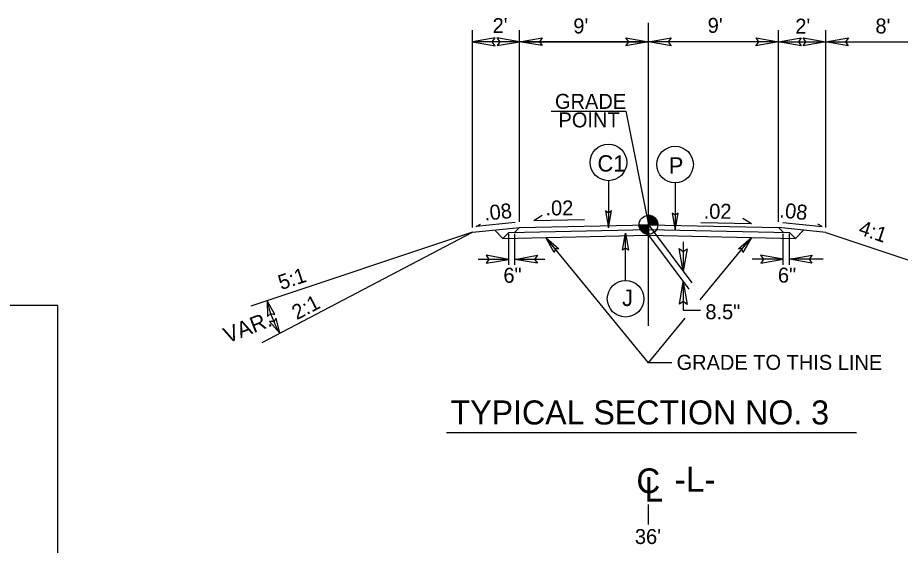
# Model space of a CAD drawing. Extents: x 1718167 to 1721223, y 797898 to 799800.
# Drawn here: x 1719514 to 1719936.5, y 798300.3 to 798552.9 of the extents above; entities that cross this region are included whole.
import ezdxf

# ---------------------------------------------------------------- set-up
doc = ezdxf.new("R2010")
doc.units = 0
for name, color, linetype in [('Old_Level_1', 7, 'Continuous'), ('Old_Level_2', 7, 'Continuous'), ('Prop Dimension Text', 7, 'Continuous'), ('Prop Terminator CELL', 7, 'Continuous'), ('Typical ID Circle CELL', 7, 'Continuous'), ('Typical Slope Point Local CELL', 7, 'Continuous'), ('Typical Terminator CELL', 7, 'Continuous'), ('Typical Text Centerline CELL', 7, 'Continuous'), ('Typical Text Grade Point CELL', 7, 'Continuous'), ('Typical Text ID Circle CELL', 7, 'Continuous'), ('Typical Text Label CELL', 7, 'Continuous')]:
    doc.layers.add(name, color=color, linetype=linetype)

# ---------------------------------------------------------------- blocks, each defined once
blk = doc.blocks.new('TERMINATOR')
at = {"layer": 'Typical Terminator CELL'}
blk.add_lwpolyline([(-0.469, 0.081), (0, 0), (-0.471, -0.083), (-0.411, 0)], close=True, dxfattribs=at)

msp = doc.modelspace()

# ---------------------------------------------------------------- linework, layer by layer
at = {"layer": 'Old_Level_1'}
for p, q in [((1719731.69, 798452.53), (1719731.67, 798546.87)), ((1719754.2, 798455.14), (1719754.22, 798546.88)), ((1719878.2, 798455.11), (1719878.22, 798546.86)), ((1719900.75, 798452.51), (1719900.77, 798546.84)), ((1719754.22, 798541.37), (1719731.67, 798541.36)), ((1719815.92, 798541.35), (1719754.22, 798541.37)), ((1719755.92, 798541.37), (1719815.92, 798541.35)), ((1719878.22, 798541.34), (1719815.92, 798541.35)), ((1719878.22, 798541.34), (1719900.76, 798541.34)), ((1719900.76, 798541.34), (1719955.79, 798541.33)), ((1719769.42, 798508.11), (1719805.11, 798508.1)), ((1719805.11, 798508.1), (1719815.9, 798453.71)), ((1719815.9, 798453.71), (1719815.91, 798458.21)), ((1719731.69, 798450.15), (1719754.24, 798452.44)), ((1719752.17, 798454.86), (1719733.45, 798452.96)), ((1719733.45, 798452.96), (1719735.53, 798454)), ((1719811.4, 798453.71), (1719815.9, 798453.71)), ((1719815.89, 798449.21), (1719815.9, 798453.71)), ((1719815.9, 798453.71), (1719815.89, 798449.21)), ((1719820.4, 798453.71), (1719815.9, 798453.71)), ((1719815.9, 798453.71), (1719836.72, 798425.99)), ((1719900.75, 798450.13), (1719878.2, 798452.42)), ((1719880.27, 798454.83), (1719898.99, 798452.93)), ((1719898.99, 798452.93), (1719896.91, 798453.97)), ((1719731.69, 798450.15), (1719625.59, 798414.76)), ((1719749.03, 798434.58), (1719749.03, 798449.37)), ((1719751.96, 798434.58), (1719751.96, 798449.37)), ((1719815.9, 798448.71), (1719835.3, 798422.88)), ((1719880.42, 798434.65), (1719880.43, 798449.43)), ((1719883.35, 798434.64), (1719883.35, 798449.43)), ((1719900.75, 798450.13), (1719955.77, 798431.77)), ((1719815.99, 798387.74), (1719766.8, 798447.69)), ((1719832.58, 798445.57), (1719832.58, 798431.51)), ((1719840.7, 798417.85), (1719865.18, 798447.69)), ((1719749.03, 798437.21), (1719734.34, 798437.21)), ((1719766.3, 798437.21), (1719751.96, 798437.21)), ((1719880.42, 798437.27), (1719865.53, 798437.27)), ((1719899.48, 798437.28), (1719883.35, 798437.27)), ((1719832.58, 798426.51), (1719832.58, 798412.85)), ((1719832.58, 798412.85), (1719840.85, 798412.85)), ((1719815.99, 798387.74), (1719833.5, 798409.08)), ((1719827.04, 798387.74), (1719815.99, 798387.74))]:
    msp.add_line(p, q, dxfattribs=at)
for points in [[(1719815.95, 798458.21), (1719815.95, 798458.21), (1719815.94, 798453.71)], [(1719816.04, 798458.21), (1719816.03, 798453.71)], [(1719816.13, 798458.2), (1719816.12, 798453.71)], [(1719816.22, 798458.2), (1719816.21, 798453.71)], [(1719816.31, 798458.19), (1719816.3, 798453.71)], [(1719816.4, 798458.18), (1719816.39, 798453.71)], [(1719816.49, 798458.17), (1719816.48, 798453.71)], [(1719816.58, 798458.16), (1719816.57, 798453.71)], [(1719816.67, 798458.15), (1719816.66, 798453.71)], [(1719816.76, 798458.13), (1719816.75, 798453.71)], [(1719816.85, 798458.11), (1719816.84, 798453.71)], [(1719816.94, 798458.09), (1719816.93, 798453.71)], [(1719817.03, 798458.07), (1719817.02, 798453.71)], [(1719817.12, 798458.04), (1719817.11, 798453.71)], [(1719817.21, 798458.02), (1719817.2, 798453.71)], [(1719817.3, 798457.99), (1719817.29, 798453.71)], [(1719817.39, 798457.96), (1719817.38, 798453.71)], [(1719817.48, 798457.93), (1719817.47, 798453.71)], [(1719817.57, 798457.89), (1719817.56, 798453.71)], [(1719817.66, 798457.85), (1719817.65, 798453.71)], [(1719817.75, 798457.81), (1719817.74, 798453.71)], [(1719817.84, 798457.77), (1719817.83, 798453.71)], [(1719817.93, 798457.73), (1719817.92, 798453.71)], [(1719818.02, 798457.68), (1719818.01, 798453.71)], [(1719818.11, 798457.63), (1719818.1, 798453.71)], [(1719818.2, 798457.58), (1719818.19, 798453.71)], [(1719818.29, 798457.53), (1719818.28, 798453.71)], [(1719818.38, 798457.47), (1719818.37, 798453.71)], [(1719818.46, 798457.41), (1719818.46, 798453.71)], [(1719818.55, 798457.34), (1719818.55, 798453.71)], [(1719818.64, 798457.28), (1719818.64, 798453.71)], [(1719818.73, 798457.21), (1719818.73, 798453.71)], [(1719818.82, 798457.13), (1719818.82, 798453.71)], [(1719818.91, 798457.05), (1719818.91, 798453.71)], [(1719819, 798456.97), (1719819, 798453.71)], [(1719819.09, 798456.88), (1719819.09, 798453.71)], [(1719819.18, 798456.79), (1719819.18, 798453.71)], [(1719819.27, 798456.69), (1719819.27, 798453.71)], [(1719819.36, 798456.58), (1719819.36, 798453.71)], [(1719819.45, 798456.47), (1719819.45, 798453.71)], [(1719819.54, 798456.35), (1719819.54, 798453.71)], [(1719811.42, 798453.71), (1719811.42, 798453.22)], [(1719811.51, 798453.71), (1719811.51, 798452.69)], [(1719811.6, 798453.71), (1719811.6, 798452.37)], [(1719811.69, 798453.71), (1719811.69, 798452.1)], [(1719811.78, 798453.71), (1719811.78, 798451.89)], [(1719811.87, 798453.71), (1719811.87, 798451.7)], [(1719811.96, 798453.71), (1719811.96, 798451.53)], [(1719812.05, 798453.71), (1719812.05, 798451.37)], [(1719812.14, 798453.71), (1719812.14, 798451.23)], [(1719812.23, 798453.71), (1719812.23, 798451.1)], [(1719812.32, 798453.71), (1719812.32, 798450.98)], [(1719812.41, 798453.71), (1719812.41, 798450.87)], [(1719812.5, 798453.71), (1719812.5, 798450.76)], [(1719812.59, 798453.71), (1719812.59, 798450.66)], [(1719812.68, 798453.71), (1719812.68, 798450.56)], [(1719812.77, 798453.71), (1719812.77, 798450.47)], [(1719812.86, 798453.71), (1719812.86, 798450.39)], [(1719812.95, 798453.71), (1719812.95, 798450.31)], [(1719813.04, 798453.71), (1719813.04, 798450.23)], [(1719813.13, 798453.71), (1719813.13, 798450.16)], [(1719813.22, 798453.71), (1719813.22, 798450.09)], [(1719813.31, 798453.71), (1719813.31, 798450.03)], [(1719813.4, 798453.71), (1719813.4, 798449.97)], [(1719813.49, 798453.71), (1719813.49, 798449.91)], [(1719813.58, 798453.71), (1719813.58, 798449.85)], [(1719813.67, 798453.71), (1719813.67, 798449.8)], [(1719813.76, 798453.71), (1719813.76, 798449.75)], [(1719813.85, 798453.71), (1719813.85, 798449.7)], [(1719813.94, 798453.71), (1719813.94, 798449.66)], [(1719814.03, 798453.71), (1719814.03, 798449.62)], [(1719814.12, 798453.71), (1719814.12, 798449.58)], [(1719814.21, 798453.71), (1719814.21, 798449.54)], [(1719814.3, 798453.71), (1719814.3, 798449.5)], [(1719814.39, 798453.71), (1719814.39, 798449.47)], [(1719814.48, 798453.71), (1719814.48, 798449.44)], [(1719814.57, 798453.71), (1719814.57, 798449.41)], [(1719814.66, 798453.71), (1719814.66, 798449.39)], [(1719814.75, 798453.71), (1719814.75, 798449.36)], [(1719814.84, 798453.71), (1719814.84, 798449.34)], [(1719814.93, 798453.71), (1719814.93, 798449.32)], [(1719815.02, 798453.71), (1719815.02, 798449.3)], [(1719815.11, 798453.71), (1719815.11, 798449.28)], [(1719815.2, 798453.71), (1719815.2, 798449.27)], [(1719815.29, 798453.71), (1719815.29, 798449.25)], [(1719815.38, 798453.71), (1719815.38, 798449.24)], [(1719815.47, 798453.71), (1719815.47, 798449.23)], [(1719815.56, 798453.71), (1719815.56, 798449.22)], [(1719815.65, 798453.71), (1719815.65, 798449.22)], [(1719815.74, 798453.71), (1719815.74, 798449.21)], [(1719815.83, 798453.71), (1719815.83, 798449.21), (1719815.83, 798449.21)], [(1719819.63, 798456.22), (1719819.63, 798453.71)], [(1719819.72, 798456.08), (1719819.72, 798453.71)], [(1719819.81, 798455.93), (1719819.81, 798453.71)], [(1719819.9, 798455.77), (1719819.9, 798453.71)], [(1719819.99, 798455.58), (1719819.99, 798453.71)], [(1719820.08, 798455.37), (1719820.08, 798453.71)], [(1719820.17, 798455.12), (1719820.17, 798453.71)], [(1719820.26, 798454.81), (1719820.26, 798453.71)], [(1719820.35, 798454.35), (1719820.35, 798453.71)]]:
    msp.add_lwpolyline(points, dxfattribs=at)
msp.add_circle((1719815.9, 798453.71), 4.5, dxfattribs=at)
for start, end in [(359.9785, 89.9785), (179.9785, 269.9785)]:
    msp.add_arc((1719815.9, 798453.71), 4.5, start, end, dxfattribs=at)
at = {"layer": 'Old_Level_2'}
for p, q in [((1719761, 798455.83), (1719765.08, 798458.3)), ((1719761, 798455.83), (1719785.28, 798456.32)), ((1719865.21, 798454.27), (1719861.13, 798456.74)), ((1719865.21, 798454.27), (1719840.92, 798454.76)), ((1719815.89, 798310.32), (1719815.89, 798319.91))]:
    msp.add_line(p, q, dxfattribs=at)
at = {"layer": 'Prop Dimension Text'}
msp.add_arc((1719682.09, 798427.21), 49.64, 191.4202, 210.7503, dxfattribs=at)
at = {"layer": 'Prop Terminator CELL'}
for points in [[(1719742.47, 798543.22), (1719731.67, 798541.36), (1719742.53, 798539.44), (1719741.15, 798541.36)], [(1719743.42, 798539.5), (1719754.22, 798541.37), (1719743.36, 798543.28), (1719744.74, 798541.37)], [(1719765.02, 798539.5), (1719754.22, 798541.37), (1719765.08, 798543.28), (1719763.7, 798541.37)], [(1719805.12, 798543.22), (1719815.92, 798541.35), (1719805.06, 798539.44), (1719806.44, 798541.36)], [(1719826.72, 798539.49), (1719815.92, 798541.35), (1719826.78, 798543.27), (1719825.4, 798541.35)], [(1719867.42, 798543.2), (1719878.22, 798541.34), (1719867.36, 798539.42), (1719868.74, 798541.34)], [(1719889.02, 798539.48), (1719878.22, 798541.34), (1719889.08, 798543.26), (1719887.7, 798541.34)], [(1719889.96, 798543.2), (1719900.76, 798541.34), (1719889.9, 798539.42), (1719891.28, 798541.34)], [(1719911.56, 798539.47), (1719900.76, 798541.34), (1719911.62, 798543.25), (1719910.24, 798541.33)], [(1719834.43, 798442.31), (1719832.58, 798431.51), (1719830.65, 798442.37), (1719832.57, 798440.99)], [(1719738.23, 798435.35), (1719749.03, 798437.21), (1719738.17, 798439.13), (1719739.55, 798437.21)], [(1719762.76, 798435.35), (1719751.96, 798437.21), (1719762.82, 798439.13), (1719761.44, 798437.21)], [(1719869.63, 798435.41), (1719880.42, 798437.27), (1719869.56, 798439.19), (1719870.94, 798437.27)], [(1719894.15, 798435.41), (1719883.35, 798437.27), (1719894.21, 798439.19), (1719892.83, 798437.27)], [(1719830.74, 798415.7), (1719832.58, 798426.51), (1719834.52, 798415.65), (1719832.59, 798417.03)]]:
    msp.add_lwpolyline(points, close=True, dxfattribs=at)
at = {"layer": 'Typical ID Circle CELL'}
for p, q in [((1719796.76, 798474.85), (1719796.76, 798452.26)), ((1719828.67, 798473.85), (1719828.67, 798451.25)), ((1719804.95, 798427.07), (1719804.95, 798449.66))]:
    msp.add_line(p, q, dxfattribs=at)
for centre in [(1719796.76, 798483.6), (1719828.67, 798482.59), (1719804.95, 798418.33)]:
    msp.add_circle(centre, 8.74, dxfattribs=at)
at = {"layer": 'Typical Slope Point Local CELL'}
for p, q in [((1719754.2, 798452.43), (1719751.96, 798450.19)), ((1719754.2, 798452.43), (1719815.9, 798453.71)), ((1719815.9, 798453.71), (1719878.2, 798452.42)), ((1719878.2, 798452.42), (1719880.43, 798450.19)), ((1719631.02, 798397.42), (1719731.69, 798450.15)), ((1719746.17, 798447.26), (1719742.41, 798451.24)), ((1719749.03, 798450.13), (1719746.17, 798447.26)), ((1719746.17, 798447.26), (1719815.9, 798448.71)), ((1719749.03, 798450.13), (1719815.9, 798451.52)), ((1719815.9, 798451.52), (1719883.37, 798450.13)), ((1719815.9, 798448.71), (1719886.25, 798447.25)), ((1719883.37, 798450.13), (1719886.25, 798447.25)), ((1719886.25, 798447.25), (1719890.2, 798451.2))]:
    msp.add_line(p, q, dxfattribs=at)
msp.add_lwpolyline([(1719060.96, 798154.41), (1719533.22, 798154.41), (1719533.22, 798415.08), (1719060.96, 798415.08)], close=True, dxfattribs=at)
at = {"layer": 'Typical Text Centerline CELL'}
msp.add_line((1719815.89, 798405.37), (1719815.92, 798550.39), dxfattribs=at)
at = {"layer": 'Typical Text Label CELL'}
msp.add_line((1719719.23, 798354.28), (1719915.5, 798354.28), dxfattribs=at)

# ---------------------------------------------------------------- block references
at = {"layer": 'Prop Dimension Text'}
for p, xscale, yscale, rotation in [((1719633.43, 798417.38), 15.392576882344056, -22.0931506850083, 105.08917076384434), ((1719639.42, 798401.82), 15.392576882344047, -22.093150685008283, -62.9158393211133)]:
    msp.add_blockref('TERMINATOR', p, dxfattribs=dict(at, xscale=xscale, yscale=yscale, rotation=rotation))
at = {"layer": 'Typical Terminator CELL'}
for p, xscale, yscale, rotation in [((1719796.76, 798452.26), 17.2740059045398, -17.2740059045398, -90), ((1719828.67, 798451.25), 17.2740059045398, -17.2740059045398, -90), ((1719766.8, 798447.69), 17.274005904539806, 17.274005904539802, 129.3686714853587), ((1719804.95, 798449.66), 17.2740059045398, 17.2740059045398, 90), ((1719865.18, 798447.69), 17.27400590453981, 17.2740059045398, 50.631328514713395)]:
    msp.add_blockref('TERMINATOR', p, dxfattribs=dict(at, xscale=xscale, yscale=yscale, rotation=rotation))

# ---------------------------------------------------------------- texts
at = {"layer": 'Old_Level_1'}
for s, height, rotation, p in [("2'", 7.161, 0.012, (1719741.31, 798545.53)), ("9'", 7.161, 359.988, (1719779.95, 798545.36)), ("9'", 7.161, 359.988, (1719844.27, 798545.64)), ("2'", 7.161, 359.988, (1719886.2, 798545.25)), ("8'", 7.161, 359.988, (1719924.57, 798545.34)), ('6"', 7.161, 0.012, (1719746.48, 798426)), ('6"', 7.161, 0.012, (1719877.88, 798426.06)), ('8.5"', 7.161, 359.988, (1719843.15, 798408.54)), ('GRADE TO THIS LINE', 7.1614, 359.988, (1719829.38, 798384.33)), ("36'", 7.161, 360, (1719809.42, 798300.93))]:
    msp.add_text(s, height=height, rotation=rotation, dxfattribs=at).set_placement(p)
at = {"layer": 'Old_Level_2'}
for rotation, p in [(5.7992, (1719737.59, 798455.69)), (354.2008, (1719878.38, 798457.33))]:
    msp.add_text('.08 ', height=7.161, rotation=rotation, dxfattribs=at).set_placement(p)
at = {"layer": 'Prop Dimension Text'}
for s, rotation, p in [('GRADE', 359.988, (1719771.17, 798509.25)), ('POINT', 359.988, (1719772.86, 798500.39)), ('.02', 359.988, (1719766.62, 798458.25)), ('.02', 359.988, (1719842.35, 798456.62)), ('4:1', 341.5531, (1719916.01, 798449.3)), ('5:1', 18.4469, (1719640.08, 798422.44))]:
    msp.add_text(s, height=7.161, rotation=rotation, dxfattribs=at).set_placement(p)
at = {"layer": 'Typical Slope Point Local CELL'}
for s, height, rotation, p in [('2:1', 7.161, 27.6461, (1719647.61, 798408.02)), ('VAR. ', 7.559, 21.3523, (1719614.36, 798396.93))]:
    msp.add_text(s, height=height, rotation=rotation, dxfattribs=at).set_placement(p)
at = {"layer": 'Typical Text Centerline CELL'}
msp.add_text('C', height=11.82, dxfattribs=at).set_placement((1719810.14, 798325.31))
msp.add_text('L', height=11.82, rotation=359.9469, dxfattribs=at).set_placement((1719814.07, 798321.27))
at = {"layer": 'Typical Text Grade Point CELL'}
msp.add_text('-L-', height=12, dxfattribs=at).set_placement((1719828.42, 798325.92))
at = {"layer": 'Typical Text ID Circle CELL'}
for s, height, p in [('C1', 7.826, (1719791.52, 798479.23)), ('P', 7.83, (1719825.64, 798478.22)), ('J', 7.83, (1719803.27, 798414.86))]:
    msp.add_text(s, height=height, dxfattribs=at).set_placement(p)
at = {"layer": 'Typical Text Label CELL'}
msp.add_text('TYPICAL SECTION NO. 3', height=11.5, dxfattribs=at).set_placement((1719721.19, 798358.16))

doc.saveas('drawing.dxf')
